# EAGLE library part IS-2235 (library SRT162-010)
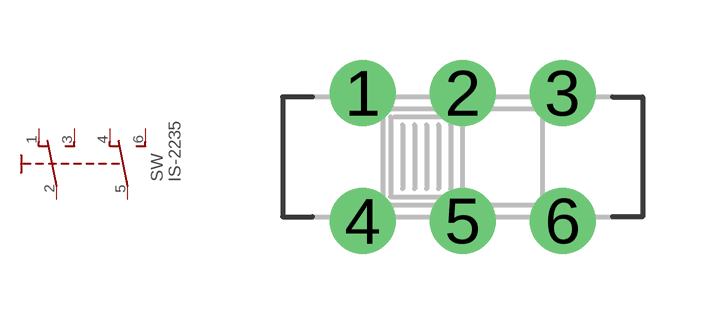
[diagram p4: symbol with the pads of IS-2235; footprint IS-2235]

Designator prefix SW

## IS-2235  [IS-2235]
1  O  pas
2  P  pas
3  S  pas
4  O1  pas
5  P1  pas
6  S1  pas

## Footprint IS-2235 (pad centres in mm)
drill 1.1 round: 1 -2.5,1.6; 2 0,1.6; 3 2.5,1.6; 4 -2.5,-1.6; 5 0,-1.6; 6 2.5,-1.6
